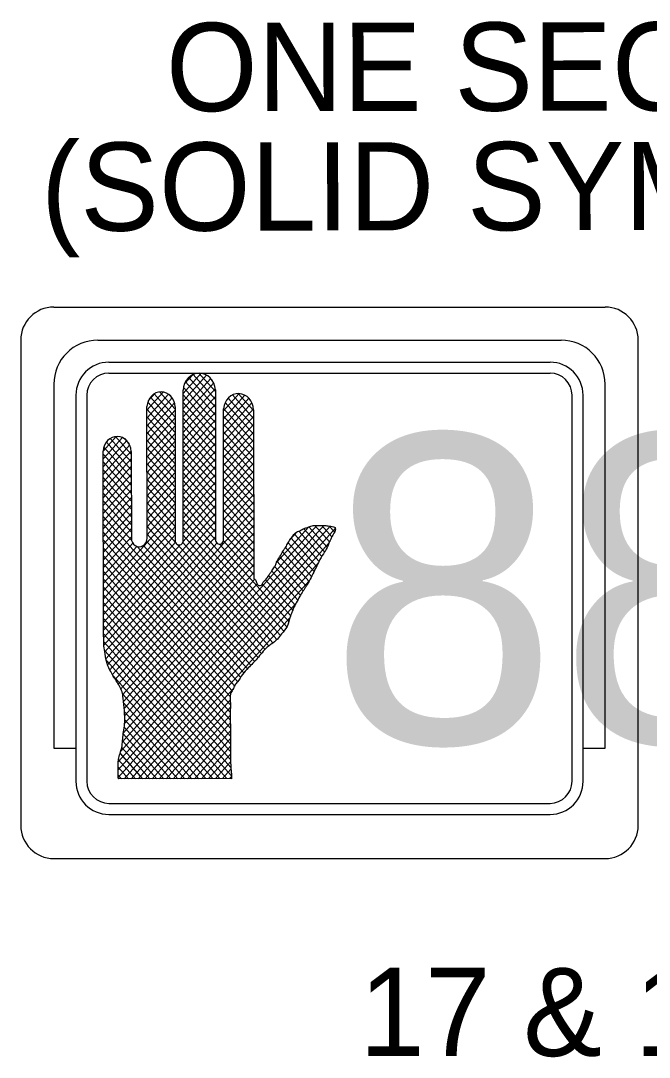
# Model space of a CAD drawing. Extents: x -218554 to 420030, y -565899 to -483460.
# Drawn here: x 419231.78 to 419260.28, y -565349.98 to -565302.99 of the extents above; entities that cross this region are included whole.
import ezdxf

# ---------------------------------------------------------------- set-up
doc = ezdxf.new("R2010")
doc.units = 0
doc.layers.add('T_Drafting', color=7, linetype='Continuous')
doc.layers.add('T_Notes', color=7, linetype='Continuous')

msp = doc.modelspace()

# ---------------------------------------------------------------- linework, layer by layer
at = {"layer": 'T_Drafting'}
for p, q in [((419233.275, -565315.971), (419258.275, -565315.971)), ((419231.775, -565317.471), (419231.775, -565339.471)), ((419235.275, -565317.471), (419256.275, -565317.471)), ((419259.775, -565339.471), (419259.775, -565317.471)), ((419235.775, -565318.471), (419255.775, -565318.471)), ((419235.775, -565318.971), (419255.775, -565318.971)), ((419239.848, -565318.967), (419240.603, -565319.807)), ((419239.14, -565319.886), (419239.961, -565318.973)), ((419239.14, -565320.239), (419240.205, -565319.056)), ((419239.14, -565320.592), (419240.389, -565319.205)), ((419239.141, -565320.946), (419240.524, -565319.409)), ((419239.193, -565319.473), (419239.594, -565319.027)), ((419239.245, -565319.359), (419240.604, -565320.869)), ((419239.391, -565319.167), (419240.604, -565320.515)), ((419239.587, -565319.031), (419240.603, -565320.161)), ((419240.314, -565319.132), (419240.456, -565319.29)), ((419233.275, -565319.471), (419233.275, -565335.971)), ((419237.501, -565320.646), (419238.239, -565319.827)), ((419237.559, -565320.229), (419237.87, -565319.883)), ((419237.829, -565319.906), (419238.775, -565320.957)), ((419238.071, -565319.822), (419238.775, -565320.603)), ((419239.147, -565326.571), (419239.139, -565319.744)), ((419239.141, -565321.299), (419240.599, -565319.679)), ((419239.155, -565319.612), (419240.605, -565321.222)), ((419240.603, -565319.725), (419240.61, -565326.503)), ((419240.97, -565320.681), (419241.675, -565319.897)), ((419241.639, -565319.897), (419242.331, -565320.666)), ((419258.275, -565335.971), (419258.275, -565319.471)), ((419234.275, -565319.971), (419234.275, -565337.471)), ((419234.775, -565319.971), (419234.775, -565337.471)), ((419237.502, -565320.999), (419238.471, -565319.922)), ((419237.502, -565321.352), (419238.639, -565320.089)), ((419237.503, -565321.705), (419238.748, -565320.321)), ((419237.537, -565320.289), (419238.776, -565321.665)), ((419237.653, -565320.065), (419238.775, -565321.311)), ((419238.496, -565319.94), (419238.665, -565320.128)), ((419239.14, -565319.948), (419240.605, -565321.576)), ((419239.14, -565320.302), (419240.605, -565321.93)), ((419239.142, -565321.652), (419240.603, -565320.028)), ((419239.142, -565322.005), (419240.604, -565320.381)), ((419240.97, -565321.034), (419241.932, -565319.965)), ((419240.971, -565321.387), (419242.122, -565320.108)), ((419240.971, -565321.74), (419242.257, -565320.311)), ((419241.046, -565320.299), (419242.332, -565321.728)), ((419241.185, -565320.099), (419242.332, -565321.374)), ((419241.377, -565319.959), (419242.331, -565321.02)), ((419256.775, -565337.471), (419256.775, -565319.971)), ((419257.275, -565337.471), (419257.275, -565319.971)), ((419237.508, -565326.443), (419237.501, -565320.478)), ((419237.501, -565320.603), (419238.776, -565322.019)), ((419237.503, -565322.058), (419238.775, -565320.645)), ((419238.774, -565320.492), (419238.781, -565326.538)), ((419239.14, -565320.656), (419240.606, -565322.284)), ((419239.142, -565322.358), (419240.604, -565320.734)), ((419240.977, -565326.535), (419240.97, -565320.587)), ((419240.971, -565320.569), (419242.332, -565322.082)), ((419240.971, -565322.094), (419242.328, -565320.586)), ((419242.331, -565320.634), (419242.34, -565328.291)), ((419237.502, -565320.957), (419238.777, -565322.373)), ((419237.502, -565321.311), (419238.777, -565322.727)), ((419237.503, -565322.411), (419238.775, -565320.999)), ((419239.141, -565321.01), (419240.606, -565322.638)), ((419239.143, -565322.711), (419240.604, -565321.087)), ((419240.97, -565320.922), (419242.333, -565322.435)), ((419240.97, -565321.276), (419242.333, -565322.789)), ((419240.972, -565322.447), (419242.331, -565320.936)), ((419240.972, -565322.8), (419242.331, -565321.29)), ((419237.503, -565321.665), (419238.777, -565323.081)), ((419237.504, -565322.765), (419238.775, -565321.352)), ((419237.504, -565323.118), (419238.776, -565321.705)), ((419239.141, -565321.364), (419240.606, -565322.992)), ((419239.142, -565321.718), (419240.607, -565323.346)), ((419239.143, -565323.064), (419240.605, -565321.44)), ((419240.971, -565321.63), (419242.333, -565323.143)), ((419240.973, -565323.153), (419242.332, -565321.643)), ((419235.513, -565322.501), (419236.109, -565321.84)), ((419235.514, -565322.855), (419236.384, -565321.888)), ((419235.514, -565323.208), (419236.58, -565322.024)), ((419235.514, -565323.561), (419236.717, -565322.224)), ((419235.66, -565322.093), (419236.787, -565323.345)), ((419235.833, -565321.931), (419236.787, -565322.991)), ((419236.072, -565321.843), (419236.787, -565322.637)), ((419236.475, -565321.938), (419236.698, -565322.185)), ((419237.503, -565322.019), (419238.778, -565323.435)), ((419237.505, -565323.471), (419238.776, -565322.058)), ((419239.142, -565322.072), (419240.607, -565323.7)), ((419239.144, -565323.417), (419240.605, -565321.793)), ((419239.144, -565323.77), (419240.606, -565322.147)), ((419240.971, -565321.984), (419242.334, -565323.497)), ((419240.973, -565323.506), (419242.332, -565321.996)), ((419235.522, -565330.742), (419235.513, -565322.499)), ((419235.513, -565322.637), (419236.788, -565324.053)), ((419235.515, -565323.914), (419236.786, -565322.502)), ((419235.546, -565322.319), (419236.788, -565323.699)), ((419236.786, -565322.513), (419236.791, -565326.444)), ((419237.503, -565322.373), (419238.778, -565323.789)), ((419237.504, -565322.727), (419238.779, -565324.143)), ((419237.505, -565323.824), (419238.777, -565322.411)), ((419239.142, -565322.426), (419240.608, -565324.054)), ((419239.144, -565324.124), (419240.606, -565322.5)), ((419240.972, -565322.338), (419242.334, -565323.851)), ((419240.972, -565322.692), (419242.334, -565324.205)), ((419240.973, -565323.859), (419242.333, -565322.349)), ((419240.974, -565324.212), (419242.333, -565322.702)), ((419235.514, -565322.991), (419236.789, -565324.407)), ((419235.515, -565324.267), (419236.787, -565322.854)), ((419237.504, -565323.081), (419238.779, -565324.497)), ((419237.505, -565324.177), (419238.777, -565322.764)), ((419237.506, -565324.53), (419238.777, -565323.117)), ((419239.143, -565322.78), (419240.608, -565324.408)), ((419239.143, -565323.134), (419240.608, -565324.762)), ((419239.145, -565324.477), (419240.606, -565322.853)), ((419240.972, -565323.046), (419242.335, -565324.559)), ((419240.974, -565324.565), (419242.333, -565323.055)), ((419235.514, -565323.345), (419236.789, -565324.761)), ((419235.515, -565324.62), (419236.787, -565323.207)), ((419235.516, -565324.973), (419236.788, -565323.56)), ((419237.505, -565323.435), (419238.779, -565324.851)), ((419237.506, -565324.883), (419238.778, -565323.47)), ((419239.144, -565323.488), (419240.609, -565325.116)), ((419239.145, -565324.83), (419240.607, -565323.206)), ((419239.146, -565325.183), (419240.607, -565323.559)), ((419240.973, -565323.4), (419242.335, -565324.913)), ((419240.975, -565324.918), (419242.334, -565323.408)), ((419235.514, -565323.699), (419236.789, -565325.115)), ((419235.515, -565324.053), (419236.79, -565325.469)), ((419235.516, -565325.326), (419236.788, -565323.913)), ((419237.505, -565323.789), (419238.78, -565325.205)), ((419237.507, -565325.236), (419238.778, -565323.823)), ((419239.144, -565323.842), (419240.609, -565325.47)), ((419239.146, -565325.536), (419240.608, -565323.912)), ((419240.973, -565323.754), (419242.336, -565325.267)), ((419240.974, -565324.108), (419242.336, -565325.621)), ((419240.975, -565325.272), (419242.334, -565323.762)), ((419240.975, -565325.625), (419242.334, -565324.115)), ((419235.515, -565324.407), (419236.79, -565325.823)), ((419235.517, -565325.68), (419236.788, -565324.267)), ((419237.505, -565324.143), (419238.78, -565325.559)), ((419237.506, -565324.497), (419238.781, -565325.913)), ((419237.507, -565325.589), (419238.779, -565324.176)), ((419237.507, -565325.942), (419238.779, -565324.53)), ((419239.144, -565324.196), (419240.61, -565325.824)), ((419239.145, -565324.55), (419240.61, -565326.178)), ((419239.146, -565325.889), (419240.608, -565324.265)), ((419240.974, -565324.462), (419242.336, -565325.975)), ((419240.976, -565325.978), (419242.335, -565324.468)), ((419235.516, -565324.761), (419236.791, -565326.177)), ((419235.517, -565326.033), (419236.789, -565324.62)), ((419235.517, -565326.386), (419236.789, -565324.973)), ((419237.506, -565324.851), (419238.781, -565326.267)), ((419237.508, -565326.296), (419238.779, -565324.883)), ((419239.143, -565326.6), (419240.609, -565324.971)), ((419239.145, -565324.904), (419240.605, -565326.526)), ((419239.147, -565326.242), (419240.608, -565324.618)), ((419240.974, -565324.816), (419242.337, -565326.329)), ((419240.976, -565326.331), (419242.335, -565324.821)), ((419235.516, -565325.115), (419236.802, -565326.544)), ((419235.516, -565325.468), (419241.894, -565332.555)), ((419235.518, -565326.739), (419236.79, -565325.326)), ((419235.52, -565328.858), (419238.78, -565325.236)), ((419235.534, -565330.963), (419240.609, -565325.325)), ((419235.815, -565332.419), (419242.335, -565325.174)), ((419235.938, -565332.636), (419242.336, -565325.527)), ((419237.507, -565325.205), (419238.797, -565326.639)), ((419239.146, -565325.258), (419243.84, -565330.474)), ((419240.975, -565325.17), (419242.337, -565326.683)), ((419240.975, -565325.524), (419242.337, -565327.037)), ((419235.517, -565325.822), (419241.746, -565332.744)), ((419235.518, -565327.092), (419236.79, -565325.679)), ((419235.52, -565329.211), (419238.78, -565325.589)), ((419235.521, -565329.564), (419238.781, -565325.942)), ((419235.545, -565331.304), (419240.609, -565325.678)), ((419236.063, -565332.85), (419242.336, -565325.88)), ((419236.198, -565336.943), (419246.044, -565326.003)), ((419236.208, -565336.578), (419245.813, -565325.906)), ((419236.313, -565336.108), (419245.524, -565325.873)), ((419236.384, -565335.676), (419245.206, -565325.873)), ((419237.507, -565325.559), (419242.853, -565331.499)), ((419237.507, -565325.913), (419242.696, -565331.679)), ((419239.146, -565325.612), (419243.7, -565330.672)), ((419239.146, -565325.966), (419243.55, -565330.859)), ((419240.976, -565325.878), (419242.338, -565327.391)), ((419243.377, -565327.552), (419244.833, -565325.935)), ((419244.842, -565325.931), (419245.673, -565326.854)), ((419245.109, -565325.874), (419245.775, -565326.614)), ((419245.426, -565325.873), (419245.888, -565326.386)), ((419245.768, -565325.9), (419245.999, -565326.155)), ((419235.517, -565326.176), (419241.612, -565332.949)), ((419235.519, -565327.445), (419236.79, -565326.032)), ((419235.519, -565327.798), (419236.791, -565326.385)), ((419235.521, -565329.917), (419238.781, -565326.295)), ((419235.594, -565331.604), (419240.61, -565326.031)), ((419235.643, -565331.903), (419240.61, -565326.384)), ((419236.187, -565333.066), (419242.337, -565326.234)), ((419237.508, -565326.267), (419242.54, -565331.859)), ((419239.147, -565326.32), (419243.393, -565331.039)), ((419240.976, -565326.232), (419242.338, -565327.745)), ((419243.979, -565326.53), (419244.321, -565326.15)), ((419244.034, -565326.447), (419245.189, -565327.73)), ((419244.185, -565326.261), (419245.301, -565327.501)), ((419244.382, -565326.127), (419245.423, -565327.284)), ((419244.607, -565326.023), (419245.551, -565327.072)), ((419235.518, -565326.53), (419241.469, -565333.143)), ((419235.518, -565326.884), (419241.357, -565333.372)), ((419235.519, -565328.151), (419236.854, -565326.669)), ((419235.52, -565328.505), (419237.035, -565326.821)), ((419235.522, -565330.27), (419238.795, -565326.633)), ((419235.522, -565330.623), (419239.005, -565326.754)), ((419235.707, -565332.185), (419240.668, -565326.673)), ((419236.198, -565337.297), (419245.737, -565326.698)), ((419236.308, -565333.285), (419242.337, -565326.587)), ((419236.403, -565333.534), (419242.337, -565326.94)), ((419237.059, -565326.829), (419242.053, -565332.378)), ((419237.336, -565326.783), (419242.216, -565332.205)), ((419237.482, -565326.592), (419242.378, -565332.032)), ((419238.889, -565326.741), (419243.025, -565331.336)), ((419239.126, -565326.651), (419243.213, -565331.192)), ((419240.783, -565326.724), (419243.933, -565330.224)), ((419240.969, -565326.577), (419242.338, -565328.099)), ((419243.782, -565326.874), (419244.959, -565328.183)), ((419243.903, -565326.655), (419245.077, -565327.959)), ((419235.518, -565327.238), (419241.273, -565333.633)), ((419236.438, -565333.848), (419242.338, -565327.293)), ((419243.518, -565327.288), (419244.718, -565328.622)), ((419243.642, -565327.073), (419244.84, -565328.404)), ((419235.519, -565327.592), (419241.284, -565333.998)), ((419236.463, -565337.356), (419245.262, -565327.58)), ((419236.468, -565334.168), (419242.338, -565327.646)), ((419243.292, -565327.744), (419244.458, -565329.039)), ((419243.398, -565327.508), (419244.589, -565328.832)), ((419235.519, -565327.946), (419241.27, -565334.336)), ((419235.519, -565328.3), (419241.271, -565334.69)), ((419236.485, -565334.857), (419242.384, -565328.302)), ((419236.487, -565334.501), (419242.338, -565327.999)), ((419242.872, -565328.338), (419244.109, -565329.713)), ((419243.02, -565328.149), (419244.217, -565329.479)), ((419243.154, -565327.944), (419244.336, -565329.258)), ((419235.52, -565328.654), (419241.287, -565335.062)), ((419236.429, -565335.273), (419242.501, -565328.526)), ((419236.782, -565337.355), (419244.843, -565328.398)), ((419242.723, -565328.526), (419244.015, -565329.962)), ((419235.52, -565329.008), (419241.288, -565335.417)), ((419235.521, -565329.362), (419241.289, -565335.771)), ((419235.521, -565329.716), (419241.289, -565336.125)), ((419237.1, -565337.355), (419244.261, -565329.399)), ((419235.521, -565330.07), (419241.291, -565336.481)), ((419237.419, -565337.354), (419243.978, -565330.067)), ((419235.522, -565330.424), (419241.305, -565336.851)), ((419235.524, -565330.78), (419241.325, -565337.226)), ((419235.537, -565331.148), (419241.118, -565337.349)), ((419235.586, -565331.557), (419240.8, -565337.35)), ((419235.658, -565331.99), (419240.482, -565337.35)), ((419235.97, -565332.69), (419240.164, -565337.35)), ((419236.4, -565333.522), (419239.847, -565337.351)), ((419237.738, -565337.354), (419241.411, -565333.273)), ((419236.446, -565333.926), (419239.529, -565337.351)), ((419238.056, -565337.353), (419241.28, -565333.772)), ((419236.478, -565334.315), (419239.211, -565337.352)), ((419238.375, -565337.353), (419241.278, -565334.128)), ((419236.49, -565334.682), (419238.893, -565337.352)), ((419238.693, -565337.353), (419241.268, -565334.492)), ((419239.012, -565337.352), (419241.276, -565334.836)), ((419236.423, -565335.315), (419238.258, -565337.353)), ((419236.47, -565335.013), (419238.575, -565337.353)), ((419239.331, -565337.352), (419241.288, -565335.177)), ((419236.388, -565335.63), (419237.94, -565337.354)), ((419239.649, -565337.351), (419241.288, -565335.53)), ((419239.968, -565337.351), (419241.289, -565335.883)), ((419233.275, -565335.971), (419234.275, -565335.971)), ((419236.278, -565336.214), (419237.304, -565337.354)), ((419236.353, -565335.944), (419237.622, -565337.354)), ((419240.286, -565337.35), (419241.289, -565336.236)), ((419257.275, -565335.971), (419258.275, -565335.971)), ((419236.213, -565336.496), (419236.986, -565337.355)), ((419240.605, -565337.35), (419241.294, -565336.584)), ((419236.198, -565337.186), (419236.351, -565337.356)), ((419236.199, -565336.834), (419236.669, -565337.355)), ((419240.924, -565337.349), (419241.309, -565336.921)), ((419241.242, -565337.349), (419241.325, -565337.257)), ((419236.223, -565337.356), (419236.198, -565337.324)), ((419241.303, -565337.349), (419236.223, -565337.356)), ((419241.326, -565337.355), (419241.303, -565337.349)), ((419235.775, -565338.471), (419255.775, -565338.471)), ((419235.775, -565338.971), (419255.775, -565338.971)), ((419233.275, -565340.971), (419258.275, -565340.971))]:
    msp.add_line(p, q, dxfattribs=at)
for centre, radius, start, end in [((419233.275, -565317.471), 1.5, 90, 180), ((419258.275, -565317.471), 1.5, 0, 90), ((419235.275, -565319.471), 2, 90, 180), ((419256.275, -565319.471), 2, 0, 90), ((419235.775, -565319.971), 1.5, 90, 180), ((419255.775, -565319.971), 1.5, 0, 90), ((419235.775, -565319.971), 1, 90, 180), ((419255.775, -565319.971), 1, 0, 90), ((419235.775, -565337.471), 1.5, 180, 270), ((419235.775, -565337.471), 1, 180, 270), ((419255.775, -565337.471), 1.5, 270, 0), ((419255.775, -565337.471), 1, 270, 0), ((419233.275, -565339.471), 1.5, 180, 270), ((419258.275, -565339.471), 1.5, 270, 0)]:
    msp.add_arc(centre, radius, start, end, dxfattribs=at)
for centre, major_axis, start_param, end_param in [((419239.872, -565319.781), (0, -0.814), 1.640121, 4.665593), ((419238.137, -565320.526), (0, -0.709), 1.618611, 4.644084), ((419241.649, -565320.654), (0, -0.758), 1.597842, 4.623315), ((419236.149, -565322.547), (0, -0.709), 1.618611, 4.644084), ((419237.149, -565326.443), (0, -0.398), 4.713646, 7.855239), ((419238.964, -565326.555), (0, -0.204), 4.633755, 7.775348), ((419240.791, -565326.518), (0, -0.207), 4.624552, 7.766145)]:
    msp.add_ellipse(centre, major_axis=major_axis, ratio=0.9, start_param=start_param, end_param=end_param, dxfattribs=at)
for points in [[(419242.339, -565328.29), (419242.39, -565328.304), (419242.459, -565328.459), (419242.548, -565328.578), (419242.6, -565328.597), (419242.687, -565328.578), (419242.741, -565328.498), (419242.899, -565328.304), (419243.022, -565328.145), (419243.093, -565328.029), (419243.163, -565327.931), (419243.286, -565327.755), (419243.356, -565327.598), (419243.461, -565327.384), (419243.532, -565327.266), (419243.655, -565327.052), (419243.794, -565326.854), (419243.9, -565326.659), (419244.022, -565326.464), (419244.129, -565326.327), (419244.286, -565326.17), (419244.479, -565326.09), (419244.585, -565326.031), (419244.744, -565325.974), (419244.884, -565325.914), (419245.096, -565325.874), (419245.272, -565325.873), (419245.5, -565325.873), (419245.712, -565325.893), (419245.958, -565325.931), (419246.028, -565325.972), (419246.044, -565326.029), (419245.941, -565326.283), (419245.87, -565326.421), (419245.801, -565326.56), (419245.73, -565326.715), (419245.694, -565326.813), (419245.554, -565327.068), (419245.345, -565327.419), (419245.063, -565327.987), (419244.711, -565328.634), (419244.431, -565329.085), (419244.272, -565329.378), (419244.133, -565329.653), (419244.05, -565329.87), (419244.007, -565329.981), (419243.85, -565330.453), (419243.606, -565330.787), (419243.412, -565331.021), (419243.131, -565331.257), (419242.955, -565331.395), (419242.498, -565331.904), (419242.095, -565332.334), (419241.831, -565332.628), (419241.602, -565332.962), (419241.488, -565333.108), (419241.392, -565333.313), (419241.286, -565333.51), (419241.287, -565333.94), (419241.27, -565334.326), (419241.27, -565334.68), (419241.288, -565335.148), (419241.288, -565335.598), (419241.289, -565336.322), (419241.308, -565336.905), (419241.325, -565337.121), (419241.325, -565337.279), (419241.326, -565337.354)], [(419236.198, -565337.324), (419236.198, -565337.01), (419236.214, -565336.483), (419236.354, -565335.935), (419236.424, -565335.309), (419236.476, -565334.957), (419236.476, -565334.272), (419236.422, -565333.705), (419236.368, -565333.412), (419236.105, -565332.923), (419235.823, -565332.434), (419235.664, -565332.023), (419235.592, -565331.593), (419235.539, -565331.26), (419235.539, -565331.046), (419235.522, -565330.742)]]:
    msp.add_spline(points, degree=3, dxfattribs=at)

# ---------------------------------------------------------------- texts
for s, height, p in [('ONE SECTION', 4, (419238.361, -565307.093)), ('(SOLID SYMBOL)', 4, (419232.695, -565312.518)), ('88', 14, (419245.74, -565335.749))]:
    msp.add_text(s, height=height, rotation=0.072, dxfattribs=at).set_placement(p)
at = {"layer": 'T_Notes'}
msp.add_text('17 & 18', height=4, dxfattribs=at).set_placement((419247.126, -565349.923))

doc.saveas('drawing.dxf')
